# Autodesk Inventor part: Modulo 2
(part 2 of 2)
body "Solid190"
feature "Pattern of M2.44:82"
body "Solid191"
feature "Pattern of M2.44:83"
body "Solid192"
feature "Pattern of M2.44:84"
body "Solid193"
feature "Pattern of M2.44:85"
body "Solid194"
feature "Pattern of M2.44:86"
body "Solid195"
feature "Pattern of M2.44:87"
body "Solid196"
feature "Pattern of M2.44:88"
body "Solid197"
feature "Pattern of M2.44:89"
body "Solid198"
feature "Pattern of M2.44:90"
body "Solid199"
feature "Pattern of M2.44:91"
body "Solid200"
feature "Pattern of M2.44:92"
body "Solid201"
feature "Pattern of M2.44:93"
body "Solid202"
feature "Pattern of M2.44:94"
body "Solid203"
feature "Pattern of M2.44:95"
body "Solid204"
feature "Pattern of M2.44:96"
body "Solid205"
feature "Pattern of M2.44:97"
body "Solid206"
feature "Pattern of M2.44:98"
body "Solid207"
feature "Pattern of M2.44:99"
body "Solid208"
feature "Pattern of M2.44:100"
body "Solid209"
feature "Pattern of M2.44:101"
body "Solid210"
feature "Pattern of M2.44:102"
body "Solid211"
feature "Pattern of M2.44:103"
body "Solid212"
body "Solid213"
body "Solid214"
body "Solid215"
body "Solid216"
body "Solid217"
body "Solid218"
body "Solid219"
body "Solid220"
body "Solid221"
body "Solid222"
body "Solid223"
body "Solid224"
body "Solid225"
body "Solid226"
body "Solid227"
body "Solid228"
body "Solid229"
body "Solid230"
body "Solid231"
body "Solid232"
body "Solid233"
body "Solid234"
body "Solid235"
body "Solid236"
body "Solid237"
body "Solid238"
body "Solid239"
body "Solid240"
body "Solid241"
body "Solid242"
body "Solid243"
body "Solid244"
body "Solid245"
body "Solid246"
body "Solid247"
body "Solid248"
body "Solid249"
body "Solid250"
body "Solid251"
body "Solid252"
body "Solid253"
body "Solid254"
body "Solid255"
body "Solid256"
body "Solid257"
body "Solid258"
body "Solid259"
body "Solid260"
body "Solid261"
body "Solid262"
body "Solid263"
body "Solid264"
body "Solid265"
node "Cimento"
move_body "Move1" dims "d414" = -10
move_body "Move2" dims "d417" = -10
other parameters: "T_P_L" = 115 [user parameter; used in 102 equation terms], "T_P_P" = 58 [user parameter; used in 15 equation terms], "A_P_L" = 115 [user parameter], "A_P_P" = 58 [user parameter], "d267" = 15, "d412" = 0, "d413" = 0, "d415" = 0, "d416" = 0
